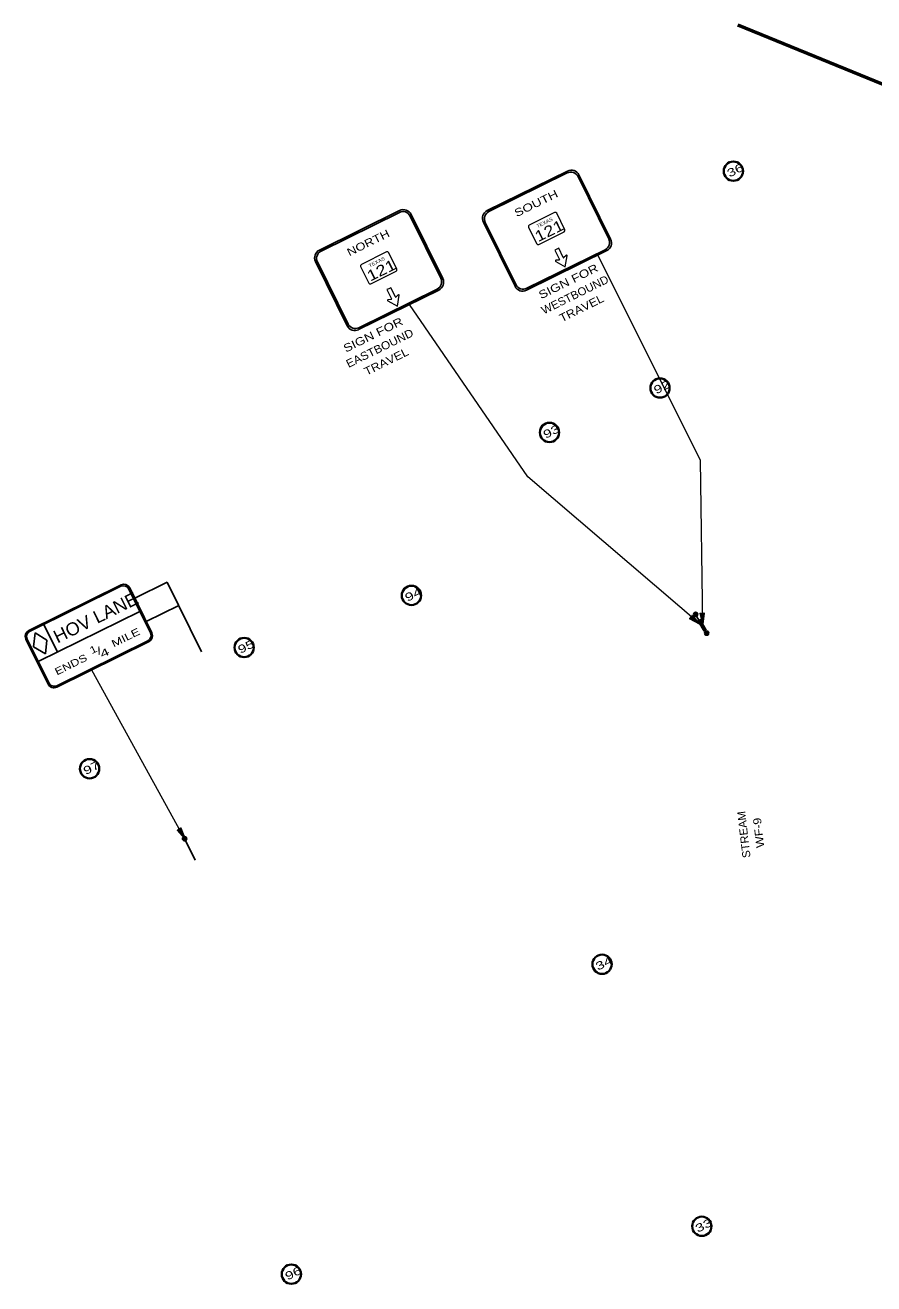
# Model space of a CAD drawing. Extents: x 2356431 to 2371438, y 6972864 to 6982525.
# Drawn here: x 2362847 to 2364327, y 6977634 to 6979829 of the extents above; entities that cross this region are included whole.
import ezdxf
from ezdxf.enums import TextEntityAlignment as Align

# ---------------------------------------------------------------- set-up
doc = ezdxf.new("R2010")
doc.units = 0
doc.header["$LTSCALE"] = 5.6
for name, color, linetype, lineweight in [('1', 7, 'Continuous', 25), ('13', 7, 'Continuous', 13), ('17', 7, 'Continuous', 35), ('48', 7, 'Continuous', 25), ('53', 7, 'Continuous', 13)]:
    doc.layers.add(name, color=color, linetype=linetype, lineweight=lineweight)
doc.layers.add('63', color=7, linetype='Continuous')

msp = doc.modelspace()

# ---------------------------------------------------------------- hatches: boundary and pattern name
at = {"layer": '48'}
for points in [[(2364023.301, 6978785.567), (2364010.252, 6978800.096), (2364005.872, 6978794.393)], [(2364020.252, 6978801.854, 1), (2364012.803, 6978801.405, 1)], [(2364029.247, 6978784.407), (2364031.514, 6978803.804), (2364024.339, 6978803.317)], [(2364039.46, 6978769.24, 1), (2364032.01, 6978768.79, 1)], [(2363125.376, 6978410.752), (2363118.534, 6978429.043), (2363112.375, 6978425.333)], [(2363128.738, 6978410.387, 1), (2363121.275, 6978410.472, 1)]]:
    msp.add_hatch(color=256, dxfattribs=at).paths.add_polyline_path(points)

# ---------------------------------------------------------------- linework, layer by layer
at = {"layer": '1', "lineweight": 53}
msp.add_line((2365578.634, 6979221.374), (2364090.226, 6979829.17), dxfattribs=at)
at = {"layer": '1'}
for p, q in [((2363038.096, 6978830.035), (2363094.671, 6978857.958)), ((2363094.671, 6978857.958), (2363154.673, 6978736.384)), ((2363058.084, 6978789.153), (2363114.811, 6978817.148))]:
    msp.add_line(p, q, dxfattribs=at)
at = {"layer": '17'}
for centre in [(2364082.349, 6979574.612), (2363954.354, 6979196.488), (2363761.476, 6979118.995), (2363520.701, 6978834.805), (2363228.844, 6978743.957), (2362959.226, 6978532.639), (2363853.246, 6978191.731), (2364027.385, 6977734.745), (2363311.246, 6977651.266)]:
    msp.add_circle(centre, 16.828, dxfattribs=at)
at = {"layer": '48'}
for p, q in [((2363792.9, 6979574.804), (2363652.999, 6979505.788)), ((2363792.465, 6979571.447), (2363655.928, 6979504.074)), ((2363864.846, 6979456.531), (2363811.296, 6979565.07)), ((2363868.209, 6979456.094), (2363812.979, 6979567.992)), ((2363500.017, 6979506.049), (2363360.116, 6979437.033)), ((2363499.582, 6979502.692), (2363363.045, 6979435.319)), ((2363571.963, 6979387.776), (2363518.413, 6979496.315)), ((2363575.326, 6979387.339), (2363520.096, 6979499.237)), ((2363646.179, 6979485.681), (2363701.385, 6979373.784)), ((2363649.55, 6979485.237), (2363703.083, 6979376.721)), ((2363721.493, 6979366.98), (2363861.388, 6979436.002)), ((2363721.928, 6979370.335), (2363858.452, 6979437.699)), ((2363353.296, 6979416.926), (2363408.502, 6979305.029)), ((2363356.667, 6979416.482), (2363410.2, 6979307.966)), ((2363428.61, 6979298.225), (2363568.505, 6979367.247)), ((2363429.045, 6979301.58), (2363565.569, 6979368.944)), ((2362853.061, 6978773.735), (2363014.117, 6978853.215)), ((2362855.25, 6978772.475), (2363013.774, 6978850.719)), ((2363065.466, 6978769.806), (2363027.912, 6978845.922)), ((2363029.177, 6978848.108), (2363067.98, 6978769.478)), ((2363067.98, 6978769.478), (2363029.177, 6978848.108)), ((2362869.664, 6978719.431), (2363047.113, 6978807.015)), ((2364016.535, 6978801.635), (2364035.7, 6978768.932)), ((2364020.405, 6978791.159), (2364031.4, 6978772.398)), ((2364023.936, 6978793.261), (2364035.032, 6978774.326)), ((2362861.337, 6978745.276), (2362864.069, 6978769.397)), ((2362864.069, 6978769.397), (2362884.878, 6978756.894)), ((2362879.149, 6978784.272), (2362903.025, 6978735.895)), ((2362847.951, 6978758.667), (2362886.756, 6978680.031)), ((2362850.466, 6978758.339), (2362888.026, 6978682.225)), ((2362861.337, 6978745.276), (2362882.145, 6978732.773)), ((2362882.145, 6978732.773), (2362884.878, 6978756.894)), ((2363062.873, 6978754.415), (2362901.825, 6978674.919)), ((2363060.673, 6978755.681), (2362902.151, 6978677.439)), ((2363125.311, 6978409.848), (2363143.355, 6978373.263))]:
    msp.add_line(p, q, dxfattribs=at)
at = {"layer": '48', "lineweight": 13}
for p, q in [((2363770.335, 6979502.464), (2363726.181, 6979480.683)), ((2363788.225, 6979472.553), (2363774.1, 6979501.192)), ((2363724.9, 6979476.918), (2363739.032, 6979448.287)), ((2363742.799, 6979447.005), (2363786.946, 6979468.785)), ((2363477.452, 6979433.709), (2363433.298, 6979411.928)), ((2363495.342, 6979403.798), (2363481.217, 6979432.437)), ((2363432.017, 6979408.163), (2363446.149, 6979379.532)), ((2363449.916, 6979378.25), (2363494.063, 6979400.03)), ((2363723.844, 6979041.381), (2363517.236, 6979341.952)), ((2363988.657, 6978815.162), (2363723.844, 6979041.381)), ((2364023.301, 6978785.567), (2363988.275, 6978815.488)), ((2362962.423, 6978704.831), (2363125.007, 6978410.429))]:
    msp.add_line(p, q, dxfattribs=at)
msp.add_lwpolyline([(2364029.247, 6978784.407), (2364024.752, 6979070.693), (2363845.964, 6979428.392)], dxfattribs=at)
at = {"layer": '48'}
for points in [[(2364023.301, 6978785.567), (2364010.252, 6978800.096), (2364005.872, 6978794.393)], [(2364029.247, 6978784.407), (2364031.514, 6978803.804), (2364024.339, 6978803.317)], [(2363125.376, 6978410.752), (2363118.534, 6978429.043), (2363112.375, 6978425.333)]]:
    msp.add_lwpolyline(points, close=True, dxfattribs=at)
for centre in [(2364016.528, 6978801.63), (2364035.735, 6978769.015), (2363125.007, 6978410.429)]:
    msp.add_circle(centre, 3.732, dxfattribs=at)
for centre, radius, start, end in [((2363799.54, 6979561.346), 15.001, 26.26237, 116.26237), ((2363798.688, 6979558.835), 14.063, 26.26238, 116.26238), ((2363505.805, 6979490.08), 14.063, 26.26238, 116.26238), ((2363506.657, 6979492.591), 15.001, 26.26237, 116.26237), ((2363659.636, 6979492.316), 15.001, 116.26237, 206.26237), ((2363662.148, 6979491.464), 14.063, 116.26237, 206.26238), ((2363852.236, 6979450.309), 14.063, 296.26238, 26.26238), ((2363854.748, 6979449.457), 15.001, 296.26238, 26.26238), ((2363366.753, 6979423.561), 15.001, 116.26237, 206.26237), ((2363369.265, 6979422.709), 14.063, 116.26237, 206.26238), ((2363559.353, 6979381.554), 14.063, 296.26238, 26.26238), ((2363561.865, 6979380.702), 15.001, 296.26238, 26.26238), ((2363714.844, 6979380.427), 15.001, 206.26237, 296.26237), ((2363715.696, 6979382.938), 14.063, 206.26238, 296.26238), ((2363421.961, 6979311.672), 15.001, 206.26237, 296.26237), ((2363422.813, 6979314.183), 14.063, 206.26238, 296.26238), ((2363018.454, 6978841.245), 10.548, 26.26515, 116.26515), ((2363019.093, 6978843.128), 11.251, 26.26515, 116.26515), ((2362858.04, 6978763.646), 11.251, 116.26456, 206.26456), ((2362859.923, 6978763.008), 10.548, 116.26456, 206.26456), ((2363056.007, 6978765.138), 10.548, 296.26515, 26.26515), ((2363057.89, 6978764.499), 11.251, 296.26515, 26.26515), ((2362896.846, 6978685.009), 11.251, 206.26456, 296.26456), ((2362897.485, 6978686.893), 10.548, 206.26456, 296.26456)]:
    msp.add_arc(centre, radius, start, end, dxfattribs=at)
at = {"layer": '48', "lineweight": 13}
for centre, start, end in [((2363771.578, 6979499.95), 26.25867, 116.25867), ((2363727.42, 6979478.165), 116.25867, 206.25867), ((2363785.706, 6979471.312), 296.25867, 26.25867), ((2363741.548, 6979449.528), 206.25867, 296.25867), ((2363478.695, 6979431.195), 26.25867, 116.25867), ((2363434.537, 6979409.41), 116.25867, 206.25867), ((2363492.823, 6979402.557), 296.25867, 26.25867), ((2363448.665, 6979380.773), 206.25867, 296.25867)]:
    msp.add_arc(centre, 2.813, start, end, dxfattribs=at)
at = {"layer": '53'}
for p, q in [((2363790.465, 6979427.771), (2363786.626, 6979423.832)), ((2363789.155, 6979407.955), (2363792.188, 6979426.868)), ((2363772.336, 6979417.235), (2363789.155, 6979407.955)), ((2363778.178, 6979419.697), (2363772.658, 6979419.138)), ((2363497.582, 6979359.016), (2363493.743, 6979355.077)), ((2363485.295, 6979350.942), (2363479.775, 6979350.383)), ((2363492.645, 6979355.206), (2363492.626, 6979355.203))]:
    msp.add_line(p, q, dxfattribs=at)
for points in [[(2363785.509, 6979423.958), (2363777.741, 6979440.089), (2363774.347, 6979438.447), (2363770.861, 6979436.738), (2363778.767, 6979420.711)], [(2363492.626, 6979355.203), (2363484.858, 6979371.334), (2363481.464, 6979369.692), (2363477.978, 6979367.983), (2363485.884, 6979351.956)], [(2363479.453, 6979348.48), (2363496.272, 6979339.2), (2363499.305, 6979358.113)]]:
    msp.add_lwpolyline(points, dxfattribs=at)
for centre, radius, start, end in [((2363786.136, 6979424.255), 0.675, 205.87407, 315.85718), ((2363791.192, 6979427.051), 1.012, 350.61257, 135.99371), ((2363772.793, 6979418.127), 1.012, 95.75444, 241.13558), ((2363778.119, 6979420.367), 0.675, 275.89097, 25.87407), ((2363498.309, 6979358.296), 1.012, 350.61257, 135.99371), ((2363479.91, 6979349.372), 1.012, 95.75444, 241.13558), ((2363485.236, 6979351.612), 0.675, 275.89097, 25.87407), ((2363493.253, 6979355.5), 0.675, 205.87407, 315.85718)]:
    msp.add_arc(centre, radius, start, end, dxfattribs=at)

# ---------------------------------------------------------------- texts
at = {"layer": '1'}
for s, width, p in [('MILE', 1.35, (2363024.974, 6978755.836)), ('1', 1.3, (2362968.335, 6978734.905)), ('/', 1.7, (2362978.557, 6978732.846)), ('4', 1.75, (2362988.043, 6978729.119)), ('ENDS', 1.3, (2362929.29, 6978708.613))]:
    msp.add_text(s, height=12.54, rotation=26.343, dxfattribs=dict(at, width=width)).set_placement(p, align=Align.CENTER)
at = {"layer": '13'}
for s, width, p in [('STREAM', 1.05, (2364107.566, 6978418.67)), ('WF-9', 1.15, (2364133.385, 6978421.728))]:
    msp.add_text(s, height=14, rotation=96.755, dxfattribs=dict(at, width=width)).set_placement(p, align=Align.CENTER)
at = {"layer": '17'}
for s, width, p in [('36', 1.4, (2364088.645, 6979569.912)), ('92', 1.4, (2363960.649, 6979191.788)), ('93', 1.4, (2363767.771, 6979114.295)), ('94', 1.45, (2363526.995, 6978830.105)), ('95', 1.4, (2363235.14, 6978739.257)), ('97', 1.4, (2362965.47, 6978527.914)), ('34', 1.45, (2363859.541, 6978187.033)), ('33', 1.45, (2364033.681, 6977730.045)), ('96', 1.4, (2363317.541, 6977646.565))]:
    msp.add_text(s, height=14, rotation=26.268, dxfattribs=dict(at, width=width)).set_placement(p, align=Align.CENTER)
at = {"layer": '48'}
for s, height, rotation, width, p in [('SOUTH', 13.5, 26.262, 1.3, (2363741.115, 6979512.431)), ('NORTH', 13.5, 26.262, 1.25, (2363448.231, 6979443.676)), ('HOV LANE', 22.5, 26.264, 1.05, (2362974.838, 6978786.253))]:
    msp.add_text(s, height=height, rotation=rotation, dxfattribs=dict(at, width=width)).set_placement(p, align=Align.CENTER)
for s, height, width, p in [('TEXAS', 6, 1.15, (2363740.81, 6979475.525)), ('121', 18.75, 1.25, (2363741.773, 6979450.633)), ('TEXAS', 6, 1.15, (2363447.927, 6979406.77)), ('121', 18.75, 1.25, (2363448.89, 6979381.878))]:
    msp.add_text(s, height=height, rotation=26.259, dxfattribs=dict(at, width=width)).set_placement(p)
at = {"layer": '63'}
for s, width, p in [('SIGN FOR', 1.25, (2363797.507, 6979376.111)), ('WESTBOUND', 1.05, (2363809.014, 6979352.797)), ('TRAVEL', 1.15, (2363820.521, 6979329.482)), ('SIGN FOR', 1.25, (2363456.913, 6979282.982)), ('EASTBOUND', 1.1, (2363468.42, 6979259.668)), ('TRAVEL', 1.15, (2363479.927, 6979236.353))]:
    msp.add_text(s, height=14, rotation=26.268, dxfattribs=dict(at, width=width)).set_placement(p, align=Align.CENTER)

doc.saveas('drawing.dxf')
